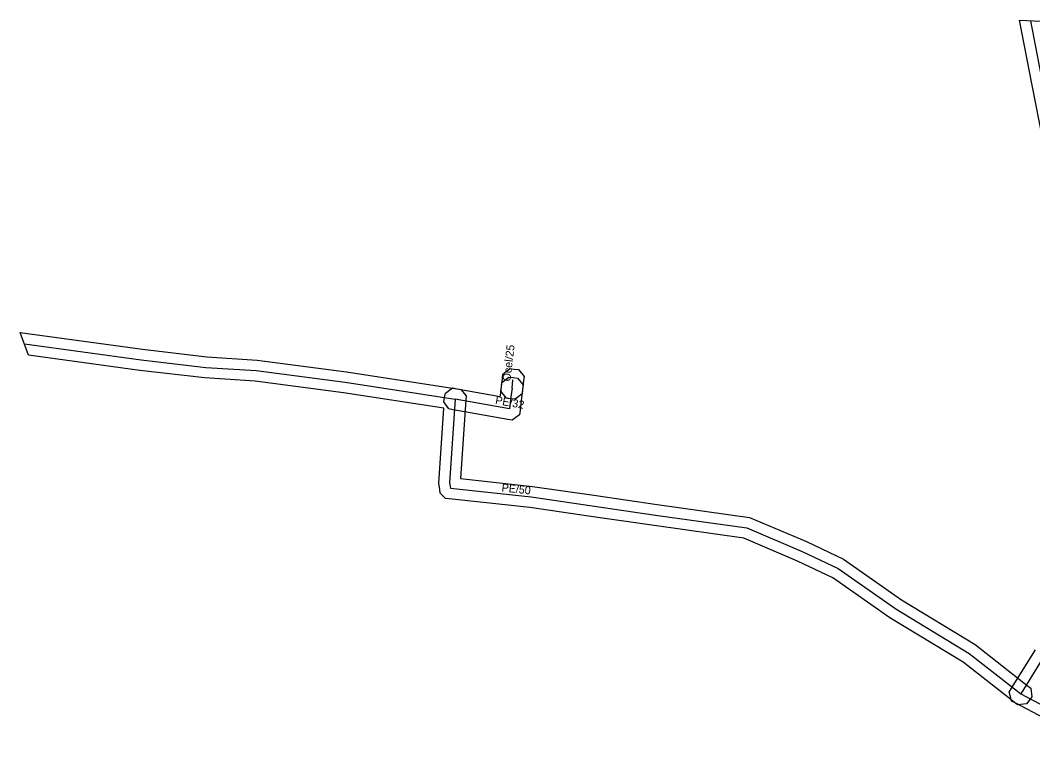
# Model space of a CAD drawing. Extents: x -678368 to -678136, y -1057358 to -1057053.
# Drawn here: x -678368.4 to -678273.5, y -1057121 to -1057052.8 of the extents above; entities that cross this region are included whole.
import ezdxf

# ---------------------------------------------------------------- set-up
doc = ezdxf.new("R2010")
doc.units = 0
for name, color, linetype in [('1', 7, 'Continuous'), ('24', 7, 'Continuous'), ('30', 7, 'Continuous')]:
    doc.layers.add(name, color=color, linetype=linetype)

msp = doc.modelspace()

# ---------------------------------------------------------------- linework, layer by layer
at = {"layer": '1'}
for points in [[(-678271.86, -1057067.618), (-678273.601, -1057058.712), (-678274.762, -1057052.791), (-678272.709, -1057052.871)], [(-678267.197, -1057120.972), (-678275.106, -1057116.805), (-678275.491, -1057116.602), (-678275.605, -1057116.182), (-678275.719, -1057115.763), (-678275.49, -1057115.393), (-678273.266, -1057111.806)]]:
    msp.add_lwpolyline(points, dxfattribs=at)
for points in [[(-678367.641, -1057084.168), (-678368.41, -1057082.042), (-678356.954, -1057083.628), (-678350.92, -1057084.324), (-678346.202, -1057084.634), (-678337.829, -1057085.73), (-678327.498, -1057087.322), (-678327.486, -1057087.324), (-678327.105, -1057087.387), (-678326.626, -1057087.992), (-678326.652, -1057088.376), (-678327.143, -1057095.748), (-678320.394, -1057096.478), (-678314.655, -1057097.31), (-678308.719, -1057098.17), (-678300.05, -1057099.388), (-678294.73, -1057101.658), (-678291.246, -1057103.302), (-678285.813, -1057107.112), (-678278.91, -1057111.306), (-678274.338, -1057114.886), (-678274.023, -1057115.133), (-678273.697, -1057115.389), (-678273.597, -1057116.211), (-678273.853, -1057116.537), (-678274.109, -1057116.863), (-678274.931, -1057116.963), (-678275.257, -1057116.707), (-678275.572, -1057116.46), (-678280.05, -1057112.954), (-678286.907, -1057108.788), (-678292.254, -1057105.038), (-678295.55, -1057103.482), (-678300.59, -1057101.332), (-678309.001, -1057100.15), (-678314.941, -1057099.29), (-678320.646, -1057098.462), (-678328.208, -1057097.644), (-678328.551, -1057097.607), (-678329.045, -1057097.125), (-678329.091, -1057096.783), (-678329.174, -1057096.163), (-678328.709, -1057089.158), (-678338.111, -1057087.71), (-678346.398, -1057086.626), (-678351.1, -1057086.316), (-678357.206, -1057085.612)], [(-678323.361, -1057087.563), (-678323.313, -1057087.152), (-678323.22, -1057086.364), (-678323.172, -1057085.953), (-678322.521, -1057085.44), (-678322.11, -1057085.488), (-678321.699, -1057085.536), (-678321.186, -1057086.187), (-678321.234, -1057086.598), (-678321.327, -1057087.386), (-678321.375, -1057087.797), (-678322.026, -1057088.31), (-678322.437, -1057088.262), (-678322.848, -1057088.214)], [(-678321.279, -1057086.975), (-678321.327, -1057087.386), (-678321.422, -1057088.191), (-678321.557, -1057089.337), (-678321.607, -1057089.766), (-678321.954, -1057090.023), (-678322.301, -1057090.28), (-678322.726, -1057090.204), (-678327.826, -1057089.294), (-678328.234, -1057089.222), (-678328.707, -1057088.542), (-678328.634, -1057088.134), (-678328.562, -1057087.726), (-678327.882, -1057087.253), (-678327.474, -1057087.326), (-678323.419, -1057088.049), (-678323.408, -1057087.957), (-678323.313, -1057087.152), (-678323.265, -1057086.741), (-678322.614, -1057086.228), (-678322.203, -1057086.276), (-678321.792, -1057086.324)]]:
    msp.add_lwpolyline(points, close=True, dxfattribs=at)
at = {"layer": '24'}
for points in [[(-678273.735, -1057052.831), (-678272.62, -1057058.52)], [(-678368.025, -1057083.105), (-678357.08, -1057084.62), (-678351.01, -1057085.32), (-678346.3, -1057085.63), (-678337.97, -1057086.72), (-678327.656, -1057088.309), (-678327.65, -1057088.31), (-678328.17, -1057096.129), (-678328.1, -1057096.65), (-678320.52, -1057097.47), (-678314.798, -1057098.3), (-678308.86, -1057099.16), (-678300.32, -1057100.36), (-678295.14, -1057102.57), (-678291.75, -1057104.17), (-678286.36, -1057107.95), (-678279.48, -1057112.13), (-678274.955, -1057115.673), (-678274.64, -1057115.92)], [(-678322.32, -1057087.269), (-678322.227, -1057086.481)], [(-678322.32, -1057087.269), (-678322.415, -1057088.074), (-678322.55, -1057089.22), (-678327.65, -1057088.31)], [(-678272.37, -1057112.259), (-678274.64, -1057115.92), (-678266.63, -1057120.14)]]:
    msp.add_lwpolyline(points, dxfattribs=at)

# ---------------------------------------------------------------- texts
at = {"layer": '30'}
for s, rotation, p in [('Ocel/25', 83.26907, (-678322.473, -1057086.675)), ('PE/32', 349.88311, (-678323.933, -1057088.738)), ('PE/50', 353.82579, (-678323.323, -1057096.945))]:
    msp.add_text(s, height=0.75, rotation=rotation, dxfattribs=at).set_placement(p)

doc.saveas('drawing.dxf')
